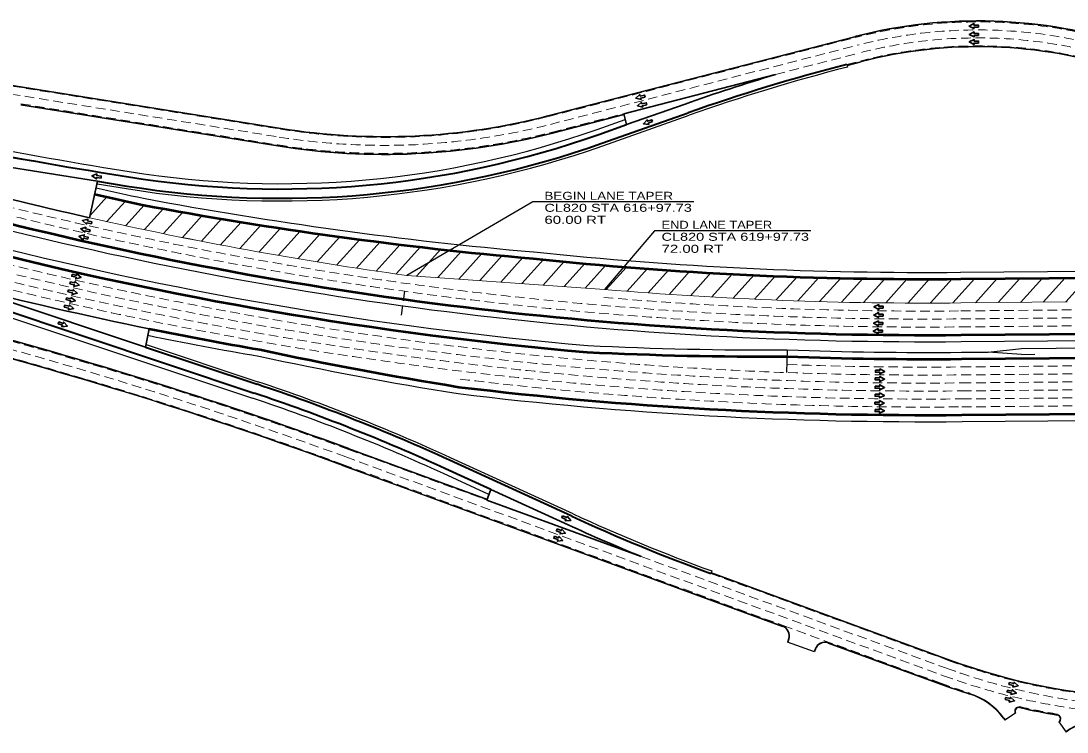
# Model space of a CAD drawing. Extents: x 2326434 to 2368642, y 6985225 to 6995090.
# Drawn here: x 2328254 to 2329823, y 6990688 to 6991755 of the extents above; entities that cross this region are included whole.
import ezdxf

# ---------------------------------------------------------------- set-up
doc = ezdxf.new("R2010")
doc.units = 0
doc.header["$LTSCALE"] = 4.8
doc.linetypes.add('MEDIUM_DASHED', pattern=[4.5, 3, -1.5])
for name, color, linetype, lineweight in [('10', 7, 'Continuous', 35), ('26', 7, 'Continuous', 25), ('27', 7, 'Continuous', 25), ('28', 7, 'Continuous', 25), ('30', 7, 'Continuous', 25), ('40', 7, 'Continuous', 35), ('5', 7, 'Continuous', 25), ('50', 7, 'MEDIUM_DASHED', 13), ('61', 7, 'Continuous', 35)]:
    doc.layers.add(name, color=color, linetype=linetype, lineweight=lineweight)

msp = doc.modelspace()

# ---------------------------------------------------------------- linework, layer by layer
at = {"layer": '10'}
for p, q in [((2329158.417, 6991616.105), (2329386.193, 6991674.871)), ((2329162.664, 6991599.644), (2329250.318, 6991630.626)), ((2329158.417, 6991616.105), (2329162.664, 6991599.644)), ((2328369.448, 6991514.635), (2327984.637, 6991576.735)), ((2328357.082, 6991459.99), (2328369.442, 6991514.609)), ((2328165.164, 6991358.166), (2328441.301, 6991265.951)), ((2328953.173, 6991036.366), (2328959.019, 6991052.33)), ((2329074.811, 6990999.218), (2328959.019, 6991052.33)), ((2328953.173, 6991036.366), (2329184.306, 6990951.729))]:
    msp.add_line(p, q, dxfattribs=at)
for centre, radius, start, end in [((2330205.012, 6988929.594), 2864.789, 106.60799, 109.46623), ((2329611.03, 6997001.375), 5681.49, 255.53357, 257.24941), ((2329611.03, 6997001.375), 5825.49, 255.62919, 258.47273), ((2330269.197, 6993603.149), 2864.789, 245.35975, 247.74692)]:
    msp.add_arc(centre, radius, start, end, dxfattribs=at)
at = {"layer": '26'}
for p, q in [((2329663.567, 6991378.13), (2330186.355, 6991383.014)), ((2329664.538, 6991274.135), (2330385.724, 6991280.873)), ((2329665.659, 6991154.14), (2330184.765, 6991158.99))]:
    msp.add_line(p, q, dxfattribs=at)
at = {"layer": '26', "lineweight": 53}
for p, q in [((2329663.66, 6991368.13), (2330141.09, 6991372.591)), ((2329664.445, 6991284.134), (2330510.625, 6991292.04)), ((2329665.566, 6991164.139), (2330162.725, 6991168.784))]:
    msp.add_line(p, q, dxfattribs=at)
at = {"layer": '26'}
for centre, radius, start, end in [((2329611.03, 6997001.375), 5635.49, 257.24941, 257.98914), ((2329549.505, 6997393.083), 6007.491, 259.34063, 264.97415), ((2329611.03, 6997001.375), 5727.49, 255.53357, 270.53529), ((2329611.03, 6997001.375), 5755.49, 255.53357, 264.94912), ((2329611.03, 6997001.375), 5623.49, 264.00179, 270.53529), ((2329611.03, 6997001.375), 5835.49, 258.47273, 260.13246), ((2329855.383, 6997053.836), 5933.578, 257.89409, 260.83136), ((2329611.03, 6997001.375), 5847.49, 263.11373, 270.53529)]:
    msp.add_arc(centre, radius, start, end, dxfattribs=at)
at = {"layer": '26', "lineweight": 53}
for centre, radius, start, end in [((2329611.03, 6997001.375), 5645.49, 257.24941, 257.98914), ((2329549.865, 6997395.485), 6019.915, 259.33925, 264.97277), ((2329611.03, 6997001.375), 5717.49, 255.53357, 270.53529), ((2329611.03, 6997001.375), 5765.49, 255.53357, 264.94912), ((2329611.03, 6997001.375), 5633.49, 264.00179, 270.53529), ((2329611.03, 6997001.375), 5825.49, 258.47273, 260.13246), ((2329862.231, 6997090.253), 5960.629, 257.89938, 260.81833), ((2329611.03, 6997001.375), 5837.49, 263.11373, 270.53529)]:
    msp.add_arc(centre, radius, start, end, dxfattribs=at)
at = {"layer": '27'}
for p, q in [((2329492.826, 6991689.99), (2329493.825, 6991686.117)), ((2329127.112, 6991567.987), (2329256.317, 6991613.655)), ((2329118.448, 6991592.501), (2329160.658, 6991607.42)), ((2328394.695, 6991532.846), (2328416.84, 6991529.272)), ((2328368.809, 6991510.687), (2328412.698, 6991503.604)), ((2328090.756, 6991359.82), (2328601.732, 6991189.182)), ((2328442.106, 6991269.9), (2328609.968, 6991213.843)), ((2329082.315, 6991015.579), (2328898.737, 6991099.783)), ((2328956.259, 6991044.794), (2328887.897, 6991076.151)), ((2329290.31, 6990929.951), (2329288.935, 6990926.195))]:
    msp.add_line(p, q, dxfattribs=at)
at = {"layer": '27', "lineweight": 40}
for p, q in [((2329125.779, 6991571.758), (2329254.984, 6991617.426)), ((2329121.114, 6991584.958), (2329162.664, 6991599.644)), ((2328371.677, 6991528.457), (2328415.565, 6991521.374)), ((2328369.446, 6991514.636), (2328413.335, 6991507.553)), ((2328065.83, 6991376.578), (2328604.266, 6991196.77)), ((2328441.301, 6991265.951), (2328608.701, 6991210.049)), ((2329080.648, 6991011.943), (2328897.069, 6991096.148)), ((2328959.019, 6991052.33), (2328891.232, 6991083.422))]:
    msp.add_line(p, q, dxfattribs=at)
for centre, radius, start, end in [((2330205.012, 6988929.594), 2850.789, 104.46691, 109.46623), ((2329284.483, 6997184.856), 5729.578, 255.53357, 260.83288), ((2328643.767, 6992935.474), 1432.395, 260.83288, 289.46623), ((2328643.767, 6992935.474), 1446.395, 260.83288, 289.46623), ((2327696.846, 6988479.491), 2878.789, 65.35975, 71.53355), ((2327696.846, 6988479.491), 2864.789, 65.35975, 71.53355), ((2330269.197, 6993603.149), 2850.789, 245.35975, 249.88799)]:
    msp.add_arc(centre, radius, start, end, dxfattribs=at)
at = {"layer": '27'}
for centre, radius, start, end in [((2330205.012, 6988929.594), 2846.789, 104.46691, 109.46623), ((2329307.501, 6997189.245), 5729.578, 255.53357, 260.83288), ((2328643.767, 6992935.474), 1424.395, 260.83288, 289.46623), ((2328643.767, 6992935.474), 1450.395, 260.83288, 289.46623), ((2327696.846, 6988479.491), 2882.789, 65.35975, 71.53355), ((2327696.846, 6988479.491), 2856.789, 65.35975, 71.53355), ((2330269.197, 6993603.149), 2846.789, 245.35975, 249.88799)]:
    msp.add_arc(centre, radius, start, end, dxfattribs=at)
at = {"layer": '28'}
for p, q in [((2329044.996, 6991613.177), (2329504.905, 6991731.834)), ((2329045.12, 6991612.693), (2329505.03, 6991731.35)), ((2327942.473, 6991706.221), (2328644.01, 6991593.884)), ((2327942.552, 6991706.715), (2328644.089, 6991594.378)), ((2329493.076, 6991689.022), (2329514.523, 6991694.555)), ((2329493.2, 6991688.537), (2329514.648, 6991694.071)), ((2328254.258, 6991629.458), (2328639.82, 6991567.718)), ((2328254.337, 6991629.951), (2328639.899, 6991568.211)), ((2329051.616, 6991587.517), (2329158.667, 6991615.137)), ((2329051.741, 6991587.033), (2329158.792, 6991614.652)), ((2329754.855, 6991263.978), (2330385.827, 6991269.873)), ((2329403.616, 6991261.631), (2329402.388, 6991227.653)), ((2329664.688, 6991258.135), (2329704.903, 6991258.511)), ((2329704.903, 6991258.511), (2329754.855, 6991263.978)), ((2329754.939, 6991254.978), (2329704.903, 6991258.511)), ((2329754.939, 6991254.978), (2329774.938, 6991255.165)), ((2328745.98, 6991113.302), (2328953.517, 6991037.305)), ((2328746.152, 6991113.772), (2328953.689, 6991037.775)), ((2328736.868, 6991088.418), (2328821.378, 6991057.472)), ((2328737.04, 6991088.888), (2328821.55, 6991057.941)), ((2328821.378, 6991057.472), (2329396.685, 6990846.803)), ((2328821.55, 6991057.941), (2329396.857, 6990847.272)), ((2329289.278, 6990927.134), (2329646.695, 6990796.253)), ((2329289.45, 6990927.603), (2329646.867, 6990796.722)), ((2329405.613, 6990827.559), (2329404.052, 6990823.296)), ((2329406.082, 6990827.388), (2329404.521, 6990823.124)), ((2329444.414, 6990808.721), (2329404.052, 6990823.296)), ((2329445.44, 6990812.975), (2329443.945, 6990808.893)), ((2329445.909, 6990812.803), (2329444.414, 6990808.721)), ((2329465.153, 6990821.731), (2329633.457, 6990760.1)), ((2329465.324, 6990822.2), (2329633.629, 6990760.57)), ((2329727.849, 6990709.029), (2329729.829, 6990706.325)), ((2329728.253, 6990709.324), (2329730.251, 6990706.595)), ((2329746.037, 6990716.651), (2329729.829, 6990706.325)), ((2329811.037, 6990703.836), (2329821.837, 6990688.205))]:
    msp.add_line(p, q, dxfattribs=at)
at = {"layer": '28', "lineweight": 53}
msp.add_line((2329664.781, 6991248.136), (2330385.967, 6991254.874), dxfattribs=at)
at = {"layer": '28'}
for centre, radius, start, end in [((2329689.814, 6991015.138), 740.165, 71.84292, 104.46691), ((2329689.814, 6991015.138), 739.665, 71.84292, 104.46691), ((2329689.814, 6991015.138), 701.665, 71.84292, 104.46691), ((2329689.814, 6991015.138), 701.165, 71.84292, 104.46691), ((2328799.48, 6992564.783), 983.268, 260.90249, 284.46691), ((2328799.48, 6992564.783), 982.768, 260.90249, 284.46691), ((2328799.48, 6992564.783), 1009.768, 260.90249, 284.46691), ((2328799.48, 6992564.783), 1009.268, 260.90249, 284.46691), ((2326481.102, 6984928.249), 6586.695, 69.88799, 75.53359), ((2326481.102, 6984928.249), 6587.195, 69.88799, 75.53359), ((2326481.102, 6984928.249), 6560.195, 69.88799, 75.53359), ((2326481.102, 6984928.249), 6560.695, 69.88799, 75.53359), ((2329380.301, 6996991.746), 5730.163, 267.23935, 270.23313), ((2329611.03, 6997001.375), 5743.49, 267.93044, 270.53529), ((2329391.527, 6990832.717), 15, 339.88799, 69.88799), ((2329391.527, 6990832.717), 15.5, 339.88799, 69.88799), ((2329459.995, 6990807.646), 15.5, 69.88799, 159.88799), ((2329459.995, 6990807.646), 15, 69.88799, 159.88799), ((2329972.578, 6991686.191), 947.728, 249.88799, 284.80383), ((2329972.578, 6991686.191), 947.228, 249.88799, 284.80383), ((2329972.578, 6991686.191), 986.228, 249.88799, 252.58153), ((2329972.578, 6991686.191), 985.728, 249.88799, 252.58153), ((2329647.567, 6990650.25), 99.5, 36.20979, 72.58153), ((2329647.567, 6990650.25), 100, 36.20979, 72.58153), ((2329750.676, 6990719.607), 6, 77.07046, 212.50002), ((2329750.676, 6990719.607), 5.5, 77.07046, 212.50002), ((2329972.578, 6991686.191), 986.228, 257.07046, 260.43355), ((2329972.578, 6991686.191), 985.728, 257.07046, 260.43355), ((2329807.761, 6990708.254), 5.5, 306.55951, 80.43355), ((2329807.761, 6990708.254), 6, 306.55951, 80.43355), ((2329870.528, 6990625.36), 80, 84.50515, 127.7674), ((2329870.528, 6990625.36), 79.5, 84.50515, 127.7674)]:
    msp.add_arc(centre, radius, start, end, dxfattribs=at)
at = {"layer": '28', "lineweight": 53}
for centre, radius, start, end in [((2329380.298, 6996991.705), 5740.113, 267.23537, 270.22914), ((2329611.03, 6997001.375), 5753.49, 267.93044, 270.53529)]:
    msp.add_arc(centre, radius, start, end, dxfattribs=at)
at = {"layer": '30', "linetype": 'MEDIUM_DASHED'}
msp.add_line((2328825.117, 6991313.928), (2328830.045, 6991349.589), dxfattribs=at)
at = {"layer": '40'}
for points in [[(2329690.311, 6991746.007), (2329690.309, 6991749.007), (2329683.502, 6991749.003), (2329683.5, 6991751.44), (2329676.303, 6991747.657), (2329683.505, 6991743.883), (2329683.504, 6991746.002)], [(2329690.539, 6991733.301), (2329690.537, 6991736.302), (2329683.73, 6991736.297), (2329683.728, 6991738.735), (2329676.531, 6991734.951), (2329683.733, 6991731.177), (2329683.732, 6991733.297)], [(2329690.458, 6991722.052), (2329690.456, 6991725.052), (2329683.65, 6991725.048), (2329683.648, 6991727.485), (2329676.45, 6991723.702), (2329683.653, 6991719.928), (2329683.652, 6991722.047)], [(2329190.421, 6991641.095), (2329189.712, 6991644.011), (2329183.098, 6991642.402), (2329182.522, 6991644.77), (2329176.419, 6991639.397), (2329184.308, 6991637.427), (2329183.808, 6991639.486)], [(2329192.922, 6991629.6), (2329192.213, 6991632.516), (2329185.599, 6991630.907), (2329185.023, 6991633.275), (2329178.92, 6991627.902), (2329186.809, 6991625.932), (2329186.308, 6991627.991)], [(2329201.525, 6991604.13), (2329200.502, 6991606.951), (2329194.103, 6991604.629), (2329193.272, 6991606.92), (2329187.793, 6991600.912), (2329195.85, 6991599.816), (2329195.127, 6991601.808)], [(2328374.713, 6991519.496), (2328375.041, 6991522.479), (2328368.275, 6991523.222), (2328368.541, 6991525.645), (2328360.971, 6991522.675), (2328367.716, 6991518.132), (2328367.947, 6991520.239)], [(2328360.134, 6991451.059), (2328360.769, 6991453.992), (2328354.116, 6991455.432), (2328354.631, 6991457.814), (2328346.795, 6991455.643), (2328353.033, 6991450.427), (2328353.481, 6991452.499)], [(2328357.449, 6991438.969), (2328358.084, 6991441.902), (2328351.431, 6991443.341), (2328351.947, 6991445.723), (2328344.11, 6991443.553), (2328350.348, 6991438.337), (2328350.797, 6991440.408)], [(2328354.887, 6991427.669), (2328355.521, 6991430.602), (2328348.869, 6991432.041), (2328349.384, 6991434.424), (2328341.548, 6991432.253), (2328347.786, 6991427.037), (2328348.234, 6991429.109)], [(2328328.595, 6991363.819), (2328327.915, 6991360.896), (2328334.544, 6991359.353), (2328333.992, 6991356.979), (2328341.861, 6991359.026), (2328335.705, 6991364.339), (2328335.225, 6991362.275)], [(2328331.335, 6991375.077), (2328330.654, 6991372.154), (2328337.284, 6991370.611), (2328336.731, 6991368.237), (2328344.6, 6991370.285), (2328338.445, 6991375.598), (2328337.964, 6991373.533)], [(2328325.722, 6991351.772), (2328325.041, 6991348.849), (2328331.671, 6991347.306), (2328331.118, 6991344.932), (2328338.987, 6991346.979), (2328332.832, 6991352.292), (2328332.351, 6991350.228)], [(2328320.176, 6991328.748), (2328319.495, 6991325.825), (2328326.125, 6991324.282), (2328325.572, 6991321.908), (2328333.441, 6991323.956), (2328327.286, 6991329.269), (2328326.805, 6991327.205)], [(2328322.868, 6991339.999), (2328322.188, 6991337.076), (2328328.817, 6991335.533), (2328328.264, 6991333.159), (2328336.134, 6991335.206), (2328329.978, 6991340.519), (2328329.497, 6991338.455)], [(2329547.54, 6991324.155), (2329547.596, 6991327.155), (2329540.79, 6991327.28), (2329540.835, 6991329.717), (2329533.566, 6991326.072), (2329540.696, 6991322.161), (2329540.735, 6991324.28)], [(2329547.207, 6991312.045), (2329547.263, 6991315.045), (2329540.457, 6991315.171), (2329540.502, 6991317.608), (2329533.233, 6991313.963), (2329540.363, 6991310.052), (2329540.402, 6991312.171)], [(2328311.532, 6991303.815), (2328310.505, 6991300.996), (2328316.901, 6991298.666), (2328316.067, 6991296.376), (2328324.125, 6991297.463), (2328318.653, 6991303.478), (2328317.928, 6991301.486)], [(2329546.911, 6991299.664), (2329546.967, 6991302.664), (2329540.161, 6991302.79), (2329540.206, 6991305.226), (2329532.938, 6991301.581), (2329540.067, 6991297.67), (2329540.106, 6991299.789)], [(2329546.583, 6991288.082), (2329546.638, 6991291.082), (2329539.832, 6991291.208), (2329539.877, 6991293.644), (2329532.609, 6991289.999), (2329539.738, 6991286.088), (2329539.777, 6991288.207)], [(2329535.545, 6991219.553), (2329535.529, 6991216.552), (2329542.335, 6991216.515), (2329542.322, 6991214.078), (2329549.543, 6991217.817), (2329542.363, 6991221.635), (2329542.352, 6991219.516)], [(2329535.723, 6991231.138), (2329535.707, 6991228.137), (2329542.513, 6991228.1), (2329542.5, 6991225.663), (2329549.721, 6991229.403), (2329542.541, 6991233.22), (2329542.529, 6991231.101)], [(2329535.411, 6991207.168), (2329535.394, 6991204.168), (2329542.201, 6991204.131), (2329542.188, 6991201.693), (2329549.408, 6991205.433), (2329542.229, 6991209.251), (2329542.217, 6991207.131)], [(2329535.235, 6991195.056), (2329535.219, 6991192.055), (2329542.025, 6991192.018), (2329542.012, 6991189.581), (2329549.233, 6991193.32), (2329542.053, 6991197.138), (2329542.042, 6991195.019)], [(2329535.101, 6991183.488), (2329535.085, 6991180.487), (2329541.892, 6991180.45), (2329541.878, 6991178.013), (2329549.099, 6991181.753), (2329541.919, 6991185.571), (2329541.908, 6991183.451)], [(2329535.252, 6991172.188), (2329535.236, 6991169.187), (2329542.043, 6991169.15), (2329542.029, 6991166.713), (2329549.25, 6991170.453), (2329542.07, 6991174.27), (2329542.059, 6991172.151)], [(2329066.756, 6991012.76), (2329065.515, 6991010.028), (2329071.713, 6991007.214), (2329070.705, 6991004.994), (2329078.824, 6991005.458), (2329073.83, 6991011.876), (2329072.954, 6991009.946)], [(2329058.407, 6990992.955), (2329057.384, 6990990.134), (2329063.783, 6990987.813), (2329062.952, 6990985.522), (2329071.009, 6990986.62), (2329065.528, 6990992.627), (2329064.806, 6990990.634)], [(2329054.396, 6990982.104), (2329053.374, 6990979.283), (2329059.773, 6990976.962), (2329058.942, 6990974.671), (2329066.999, 6990975.769), (2329061.518, 6990981.776), (2329060.795, 6990979.783)], [(2329733.921, 6990751.286), (2329733.218, 6990748.369), (2329739.835, 6990746.774), (2329739.264, 6990744.404), (2329747.149, 6990746.39), (2329741.035, 6990751.751), (2329740.538, 6990749.691)], [(2329736.702, 6990762.515), (2329735.998, 6990759.598), (2329742.616, 6990758.003), (2329742.044, 6990755.633), (2329749.93, 6990757.619), (2329743.816, 6990762.98), (2329743.319, 6990760.92)], [(2329731.14, 6990740.057), (2329730.437, 6990737.14), (2329737.054, 6990735.544), (2329736.483, 6990733.175), (2329744.368, 6990735.161), (2329738.254, 6990740.522), (2329737.758, 6990738.462)]]:
    msp.add_lwpolyline(points, close=True, dxfattribs=at)
at = {"layer": '5'}
for p, q in [((2329263.336, 6991483.856), (2329039.48, 6991483.856)), ((2329438.981, 6991440.373), (2329215.125, 6991440.373))]:
    msp.add_line(p, q, dxfattribs=at)
for points in [[(2329039.48, 6991483.856), (2329021.994, 6991483.856), (2328833.33, 6991373.363)], [(2329215.125, 6991440.373), (2329204.465, 6991440.373), (2329129.352, 6991352.383)]]:
    msp.add_lwpolyline(points, dxfattribs=at)
at = {"layer": '50'}
for p, q in [((2329045.37, 6991611.725), (2329505.28, 6991730.382)), ((2329048.368, 6991600.105), (2329508.278, 6991718.762)), ((2329386.193, 6991674.871), (2329511.275, 6991707.143)), ((2327940.418, 6991693.385), (2328641.955, 6991581.048)), ((2327942.315, 6991705.234), (2328643.852, 6991592.897)), ((2329492.826, 6991689.99), (2329514.273, 6991695.523)), ((2328254.495, 6991630.939), (2328640.057, 6991569.199)), ((2329051.366, 6991588.486), (2329158.417, 6991616.105)), ((2329664.221, 6991308.133), (2332252.529, 6991332.315)), ((2329664.109, 6991320.133), (2330154.405, 6991324.713)), ((2329664.333, 6991296.134), (2332252.641, 6991320.316)), ((2329664.893, 6991236.136), (2330386.079, 6991242.874)), ((2329665.118, 6991212.137), (2332253.426, 6991236.319)), ((2329665.23, 6991200.138), (2332253.538, 6991224.32)), ((2329665.342, 6991188.138), (2330162.501, 6991192.783)), ((2329665.454, 6991176.139), (2330162.613, 6991180.784)), ((2328745.636, 6991112.363), (2328953.173, 6991036.366)), ((2328741.51, 6991101.095), (2329638.099, 6990772.777)), ((2328737.384, 6991089.827), (2328821.894, 6991058.88)), ((2328821.894, 6991058.88), (2329397.583, 6990848.071)), ((2329184.306, 6990951.729), (2329642.225, 6990784.045)), ((2329288.935, 6990926.195), (2329646.351, 6990795.314)), ((2329397.524, 6990848.093), (2329633.973, 6990761.509))]:
    msp.add_line(p, q, dxfattribs=at)
at = {"layer": '50', "linetype": 'Continuous'}
for p, q in [((2328415.565, 6991521.374), (2327986.868, 6991590.556)), ((2328365.028, 6991495.102), (2328357.082, 6991459.99)), ((2328357.765, 6991463.009), (2328383.055, 6991491.145)), ((2328383.523, 6991454.267), (2328411.13, 6991484.982)), ((2328411.662, 6991448.176), (2328439.286, 6991478.909)), ((2328439.802, 6991442.085), (2328468.118, 6991473.589)), ((2328468.042, 6991436.106), (2328497.136, 6991468.475)), ((2328496.602, 6991430.483), (2328526.263, 6991463.482)), ((2328525.162, 6991424.86), (2328555.389, 6991458.49)), ((2328553.723, 6991419.237), (2328584.516, 6991453.497)), ((2328582.53, 6991413.889), (2328614.038, 6991448.944)), ((2328611.52, 6991408.744), (2328643.596, 6991444.43)), ((2328640.51, 6991403.599), (2328673.153, 6991439.916)), ((2328669.501, 6991398.455), (2328702.82, 6991435.524)), ((2328698.911, 6991393.778), (2328732.818, 6991431.501)), ((2328728.341, 6991389.123), (2328762.816, 6991427.479)), ((2328757.772, 6991384.468), (2328792.815, 6991423.456)), ((2328787.332, 6991379.957), (2328823.095, 6991419.746)), ((2328817.106, 6991375.685), (2328853.545, 6991416.226)), ((2328847.784, 6991372.417), (2328883.996, 6991412.706)), ((2328879.378, 6991370.169), (2328914.467, 6991409.208)), ((2328910.971, 6991367.922), (2328945.381, 6991406.205)), ((2328942.565, 6991365.674), (2328976.296, 6991403.201)), ((2328974.159, 6991363.426), (2329007.21, 6991400.198)), ((2329005.753, 6991361.178), (2329038.113, 6991397.181)), ((2329037.347, 6991358.93), (2329069.094, 6991394.251)), ((2329068.941, 6991356.682), (2329100.075, 6991391.321)), ((2329100.534, 6991354.434), (2329131.056, 6991388.391)), ((2329132.117, 6991352.174), (2329162.493, 6991385.969)), ((2329163.587, 6991349.788), (2329193.969, 6991383.589)), ((2329195.057, 6991347.402), (2329225.445, 6991381.21)), ((2329226.527, 6991345.016), (2329257.205, 6991379.147)), ((2329258.359, 6991343.033), (2329289.19, 6991377.335)), ((2328833.33, 6991373.363), (2329129.352, 6991352.383)), ((2329129.352, 6991352.383), (2328833.33, 6991373.363)), ((2329290.336, 6991341.212), (2329321.175, 6991375.523)), ((2329322.314, 6991339.391), (2329353.289, 6991373.853)), ((2329354.495, 6991337.796), (2329385.8, 6991372.625)), ((2329386.996, 6991336.557), (2329418.31, 6991371.397)), ((2329419.496, 6991335.318), (2329450.82, 6991370.169)), ((2329452.059, 6991334.148), (2329483.863, 6991369.533)), ((2329485.099, 6991333.51), (2329516.915, 6991368.907)), ((2329518.14, 6991332.871), (2329549.967, 6991368.282)), ((2329551.18, 6991332.233), (2329583.452, 6991368.137)), ((2329584.719, 6991332.148), (2329617.064, 6991368.134)), ((2329618.316, 6991332.13), (2329650.675, 6991368.132)), ((2329651.914, 6991332.112), (2329684.464, 6991368.325)), ((2330141.09, 6991372.591), (2329663.66, 6991368.13)), ((2329685.73, 6991332.335), (2329718.363, 6991368.642)), ((2329719.629, 6991332.652), (2329752.262, 6991368.958)), ((2329753.528, 6991332.969), (2329786.161, 6991369.275)), ((2329787.427, 6991333.285), (2329820.06, 6991369.592)), ((2329821.326, 6991333.602), (2329853.959, 6991369.908)), ((2329823.17, 6991333.619), (2329663.996, 6991332.132)), ((2329663.996, 6991332.132), (2329823.17, 6991333.619))]:
    msp.add_line(p, q, dxfattribs=at)
at = {"layer": '50'}
msp.add_lwpolyline([(2329665.005, 6991224.137), (2332090.455, 6991246.797), (2332253.314, 6991248.319)], dxfattribs=at)
for centre, radius, start, end in [((2329689.814, 6991015.138), 738.665, 71.84292, 104.46691), ((2329689.814, 6991015.138), 726.665, 71.84292, 104.46691), ((2329689.814, 6991015.138), 714.665, 71.84292, 104.46691), ((2329689.814, 6991015.138), 702.665, 71.84292, 104.46691), ((2328799.48, 6992564.783), 984.268, 260.90249, 284.46691), ((2328799.48, 6992564.783), 996.268, 260.90249, 284.46691), ((2328799.48, 6992564.783), 1008.268, 260.90249, 284.46691), ((2329611.03, 6997001.375), 5693.49, 255.53357, 270.53529), ((2329611.03, 6997001.375), 5705.49, 255.53357, 270.53529), ((2329611.03, 6997001.375), 5789.49, 255.53357, 270.53529), ((2329611.03, 6997001.375), 5777.49, 255.53357, 270.53529), ((2329611.03, 6997001.375), 5801.49, 255.53357, 270.53529), ((2329611.03, 6997001.375), 5813.49, 255.53357, 270.53529), ((2329611.03, 6997001.375), 5681.49, 265.1263, 270.53529), ((2326481.102, 6984928.249), 6585.695, 69.88799, 75.53359), ((2326481.102, 6984928.249), 6573.695, 69.88799, 75.53359), ((2326481.102, 6984928.249), 6561.695, 69.88799, 75.53359), ((2329611.03, 6997001.375), 5765.49, 267.9429, 270.53529), ((2329611.03, 6997001.375), 5825.49, 263.12134, 270.53529), ((2329972.578, 6991686.191), 960.728, 249.88799, 284.80383), ((2329972.578, 6991686.191), 948.728, 249.88799, 284.80383), ((2329972.578, 6991686.191), 972.728, 249.88799, 284.80383), ((2329972.578, 6991686.191), 984.728, 249.88799, 252.58153), ((2329972.578, 6991686.191), 984.728, 257.07046, 260.43355)]:
    msp.add_arc(centre, radius, start, end, dxfattribs=at)
at = {"layer": '50', "linetype": 'Continuous'}
for centre, radius, start, end in [((2329611.03, 6997001.375), 5645.49, 257.24941, 257.98914), ((2329549.865, 6997395.485), 6019.915, 259.33925, 264.97277), ((2329613.645, 6997015.752), 5696.091, 257.25567, 262.12622), ((2329611.03, 6997001.375), 5681.49, 257.24941, 262.13248), ((2329611.03, 6997001.375), 5633.49, 264.00179, 270.53529), ((2329611.03, 6997001.375), 5669.49, 265.1263, 270.53529), ((2329611.03, 6997001.375), 5669.49, 265.1263, 270.53529)]:
    msp.add_arc(centre, radius, start, end, dxfattribs=at)
at = {"layer": '61'}
msp.add_line((2328446.896, 6991293.387), (2328441.301, 6991265.951), dxfattribs=at)

# ---------------------------------------------------------------- texts
at = {"layer": '5'}
for s, width, p in [('BEGIN LANE TAPER', 1.25, (2329039.479, 6991486.856)), ('CL820 STA 616+97.73', 1.35, (2329039.479, 6991468.856)), ('60.00 RT', 1.4, (2329039.48, 6991450.856)), ('END LANE TAPER', 1.2, (2329215.124, 6991443.373)), ('CL820 STA 619+97.73', 1.35, (2329215.124, 6991425.373)), ('72.00 RT', 1.4, (2329215.125, 6991407.373))]:
    msp.add_text(s, height=12, dxfattribs=dict(at, width=width)).set_placement(p)

doc.saveas('drawing.dxf')
